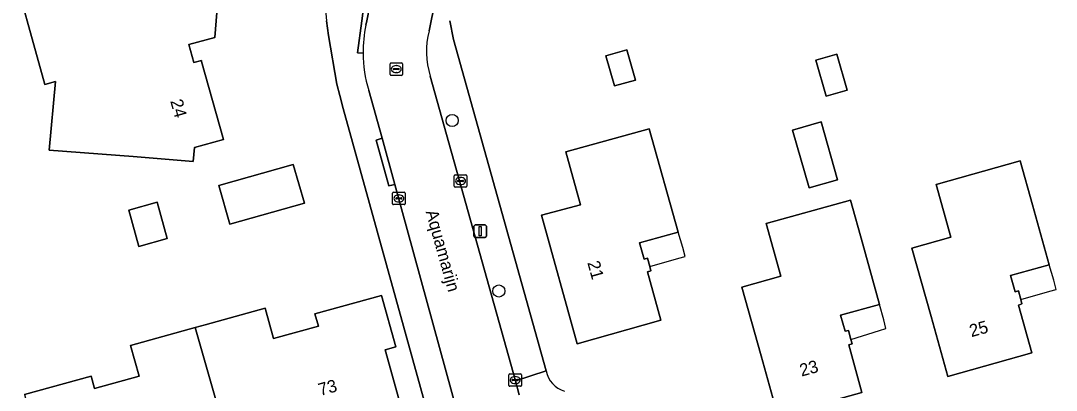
# Model space of a CAD drawing. Extents: x 159626 to 160723, y 388173 to 389416.
# Drawn here: x 159856.1 to 159939.1, y 388470.3 to 388500 of the extents above; entities that cross this region are included whole.
import ezdxf

# ---------------------------------------------------------------- set-up
doc = ezdxf.new("R2010")
doc.units = 0
for name, color, linetype in [('IMGEO_Boom', 7, 'Continuous'), ('IMGEO_Erf', 7, 'Continuous'), ('IMGEO_Kolk', 7, 'Continuous'), ('IMGEO_Lichtmast', 7, 'Continuous'), ('IMGEO_Openbare_ruimte_label', 7, 'Continuous'), ('IMGEO_Pand', 7, 'Continuous'), ('IMGEO_Pand_nummerreeks', 7, 'Continuous'), ('IMGEO_Pand_overbouw', 7, 'Continuous'), ('IMGEO_Rijbaan_lokaal_open', 7, 'Continuous'), ('IMGEO_Rioolput', 7, 'Continuous'), ('IMGEO_Voetpad_open', 7, 'Continuous')]:
    doc.layers.add(name, color=color, linetype=linetype)

msp = doc.modelspace()

# ---------------------------------------------------------------- linework, layer by layer
at = {"layer": 'IMGEO_Boom'}
for centre in [(159890.663, 388491.988), (159894.397, 388478.312)]:
    msp.add_circle(centre, 0.489, dxfattribs=at)
at = {"layer": 'IMGEO_Erf'}
for points in [[(159866.921, 388502.361), (159871.9, 388501.911), (159871.881, 388501.686), (159871.735, 388500), (159871.619, 388498.655), (159869.554, 388498.093), (159869.943, 388496.65), (159870.55, 388496.812), (159870.574, 388496.727), (159872.315, 388490.461), (159870.004, 388489.814), (159869.885, 388488.701), (159865.084, 388489.093), (159858.349, 388489.616), (159858.847, 388495.122), (159858.01, 388494.89), (159856.584, 388500), (159855.64, 388503.38)], [(159905.353, 388495.236), (159903.666, 388494.765), (159902.989, 388497.194), (159904.675, 388497.664)], [(159921.492, 388497.321), (159922.317, 388494.43), (159920.644, 388493.952), (159919.818, 388496.843)], [(159908.779, 388483.03), (159905.692, 388482.177), (159906.051, 388480.875), (159906.311, 388480.946), (159906.499, 388480.266), (159906.594, 388479.93), (159906.334, 388479.842), (159907.4, 388475.978), (159900.689, 388474.067), (159897.818, 388484.386), (159900.953, 388485.215), (159899.784, 388489.473), (159906.462, 388491.336)], [(159921.567, 388487.242), (159919.279, 388486.588), (159917.953, 388491.229), (159920.242, 388491.883)], [(159877.925, 388488.455), (159878.816, 388485.348), (159872.834, 388483.666), (159871.96, 388486.772)], [(159938.532, 388480.412), (159935.434, 388479.557), (159935.793, 388478.255), (159936.053, 388478.326), (159936.243, 388477.64), (159936.342, 388477.283), (159936.058, 388477.184), (159937.126, 388473.343), (159930.4, 388471.458), (159929.055, 388476.274), (159927.523, 388481.761), (159930.649, 388482.634), (159929.467, 388486.866), (159936.2, 388488.746), (159937.184, 388485.228)], [(159923.574, 388482.06), (159924.919, 388477.244), (159921.805, 388476.384), (159922.164, 388475.082), (159922.424, 388475.153), (159922.625, 388474.428), (159922.719, 388474.088), (159922.455, 388473.998), (159923.504, 388470.163), (159916.769, 388468.303), (159915.425, 388473.12), (159913.89, 388478.62), (159917.021, 388479.496), (159915.84, 388483.716), (159922.584, 388485.604)], [(159866.996, 388485.433), (159867.815, 388482.519), (159865.55, 388481.882), (159864.731, 388484.795)]]:
    msp.add_lwpolyline(points, close=True, dxfattribs=at)
for points in [[(159888.881, 388467.873), (159881.923, 388492.948), (159881.641, 388493.992), (159881.416, 388494.916), (159880.757, 388498.822), (159880.578, 388500)], [(159890.475, 388500), (159890.766, 388498.501), (159898.187, 388471.902)], [(159856.365, 388469.998), (159861.708, 388471.483), (159861.98, 388470.501), (159865.552, 388471.493), (159864.871, 388473.937), (159870.052, 388475.377), (159870.846, 388475.598), (159875.663, 388476.937), (159876.343, 388474.49), (159879.933, 388475.489), (159879.657, 388476.48), (159884.99, 388477.962), (159886.138, 388473.831), (159885.3, 388473.598), (159886.556, 388469.073)]]:
    msp.add_lwpolyline(points, dxfattribs=at)
for centre, radius, start, end in [((159893.604, 388501.361), 13.097, 165.53917, 185.96617), ((159900.306, 388472.34), 2.164, 191.67248, 253.04243)]:
    msp.add_arc(centre, radius, start, end, dxfattribs=at)
at = {"layer": 'IMGEO_Kolk'}
for p, q in [((159890.829, 388486.713), (159890.829, 388487.565)), ((159890.904, 388487.639), (159891.756, 388487.639)), ((159891.131, 388487.182), (159891.529, 388487.182)), ((159891.317, 388487.419), (159891.342, 388487.419)), ((159891.83, 388487.565), (159891.83, 388486.713)), ((159891.756, 388486.639), (159890.904, 388486.639)), ((159891.088, 388487.133), (159891.088, 388487.145)), ((159891.526, 388487.096), (159891.128, 388487.096)), ((159891.34, 388486.859), (159891.315, 388486.859)), ((159891.572, 388487.145), (159891.572, 388487.133)), ((159885.886, 388485.316), (159885.886, 388486.168)), ((159885.961, 388486.242), (159886.813, 388486.242)), ((159886.145, 388485.736), (159886.145, 388485.748)), ((159886.583, 388485.699), (159886.185, 388485.699)), ((159886.188, 388485.785), (159886.586, 388485.785)), ((159886.374, 388486.022), (159886.399, 388486.022)), ((159886.629, 388485.748), (159886.629, 388485.736)), ((159886.887, 388486.168), (159886.887, 388485.316)), ((159886.813, 388485.242), (159885.961, 388485.242)), ((159886.397, 388485.462), (159886.372, 388485.462)), ((159895.211, 388470.744), (159895.211, 388471.596)), ((159895.286, 388471.67), (159896.138, 388471.67)), ((159895.699, 388471.45), (159895.724, 388471.45)), ((159896.212, 388471.596), (159896.212, 388470.744)), ((159896.138, 388470.67), (159895.286, 388470.67)), ((159895.47, 388471.164), (159895.47, 388471.176)), ((159895.908, 388471.127), (159895.51, 388471.127)), ((159895.513, 388471.213), (159895.911, 388471.213)), ((159895.722, 388470.89), (159895.697, 388470.89)), ((159895.954, 388471.176), (159895.954, 388471.164))]:
    msp.add_line(p, q, dxfattribs=at)
for points in [[(159890.829, 388486.713), (159890.829, 388487.565)], [(159890.904, 388487.639), (159891.756, 388487.639)], [(159891.83, 388487.565), (159891.83, 388486.713)], [(159891.756, 388486.639), (159890.904, 388486.639)], [(159885.886, 388485.316), (159885.886, 388486.168)], [(159885.961, 388486.242), (159886.813, 388486.242)], [(159886.887, 388486.168), (159886.887, 388485.316)], [(159886.813, 388485.242), (159885.961, 388485.242)], [(159895.211, 388470.744), (159895.211, 388471.596)], [(159895.286, 388471.67), (159896.138, 388471.67)], [(159896.212, 388471.596), (159896.212, 388470.744)], [(159896.138, 388470.67), (159895.286, 388470.67)]]:
    msp.add_lwpolyline(points, dxfattribs=at)
for centre, radius, start, end in [((159890.906, 388487.563), 0.0765, 91.55205, 178.44795), ((159890.906, 388487.563), 0.0765, 91.55205, 178.44795), ((159891.128, 388487.142), 0.0403, 85.87752, 175.75265), ((159891.533, 388487.144), 0.0386, 1.73085, 96.63898), ((159891.754, 388487.563), 0.0765, 1.55205, 88.44795), ((159891.754, 388487.563), 0.0765, 1.55205, 88.44795), ((159890.906, 388486.715), 0.0765, 181.55205, 268.44795), ((159890.906, 388486.715), 0.0765, 181.55205, 268.44795), ((159891.125, 388487.132), 0.0366, 178.93798, 274.71019), ((159891.529, 388487.139), 0.043, 264.86636, 352.45326), ((159891.754, 388486.715), 0.0765, 271.55205, 358.44795), ((159891.754, 388486.715), 0.0765, 271.55205, 358.44795), ((159885.963, 388486.166), 0.0765, 91.55205, 178.44795), ((159885.963, 388486.166), 0.0765, 91.55205, 178.44795), ((159886.185, 388485.745), 0.0403, 85.87752, 175.75265), ((159886.182, 388485.735), 0.0366, 178.93798, 274.71019), ((159886.586, 388485.742), 0.043, 264.86636, 352.45326), ((159886.59, 388485.747), 0.0386, 1.73085, 96.63898), ((159886.811, 388486.166), 0.0765, 1.55205, 88.44795), ((159886.811, 388486.166), 0.0765, 1.55205, 88.44795), ((159885.963, 388485.318), 0.0765, 181.55205, 268.44795), ((159885.963, 388485.318), 0.0765, 181.55205, 268.44795), ((159886.811, 388485.318), 0.0765, 271.55205, 358.44795), ((159886.811, 388485.318), 0.0765, 271.55205, 358.44795), ((159895.288, 388471.594), 0.0765, 91.55205, 178.44795), ((159895.288, 388471.594), 0.0765, 91.55205, 178.44795), ((159896.136, 388471.594), 0.0765, 1.55205, 88.44795), ((159896.136, 388471.594), 0.0765, 1.55205, 88.44795), ((159895.288, 388470.746), 0.0765, 181.55205, 268.44795), ((159895.288, 388470.746), 0.0765, 181.55205, 268.44795), ((159895.51, 388471.173), 0.0403, 85.87752, 175.75265), ((159895.507, 388471.163), 0.0366, 178.93798, 274.71019), ((159895.911, 388471.17), 0.043, 264.86636, 352.45326), ((159895.915, 388471.175), 0.0386, 1.73085, 96.63898), ((159896.136, 388470.746), 0.0765, 271.55205, 358.44795), ((159896.136, 388470.746), 0.0765, 271.55205, 358.44795)]:
    msp.add_arc(centre, radius, start, end, dxfattribs=at)
for centre, major_axis, ratio, start_param, end_param in [((159891.316, 388487.139), (-0.387, 0.002), 0.722429, 4.712389, 7.853982), ((159891.341, 388487.139), (-0.39, 0.002), 0.717154, 1.570796, 4.712389), ((159886.373, 388485.742), (-0.387, 0.002), 0.722429, 4.712389, 7.853982), ((159886.398, 388485.742), (-0.39, 0.002), 0.717154, 1.570796, 4.712389), ((159895.698, 388471.17), (-0.387, 0.002), 0.722429, 4.712389, 7.853982), ((159895.723, 388471.17), (-0.39, 0.002), 0.717154, 1.570796, 4.712389)]:
    msp.add_ellipse(centre, major_axis=major_axis, ratio=ratio, start_param=start_param, end_param=end_param, dxfattribs=at)
at = {"layer": 'IMGEO_Lichtmast'}
for p, q in [((159892.41, 388482.71), (159892.41, 388483.51)), ((159892.41, 388483.51), (159892.41, 388482.71)), ((159892.51, 388483.61), (159893.3, 388483.61)), ((159893.3, 388483.61), (159892.51, 388483.61)), ((159893.4, 388483.51), (159893.4, 388482.71)), ((159893.4, 388482.71), (159893.4, 388483.51)), ((159893.3, 388482.61), (159892.51, 388482.61)), ((159892.51, 388482.61), (159893.3, 388482.61))]:
    msp.add_line(p, q, dxfattribs=at)
msp.add_lwpolyline([(159892.83, 388483.485), (159892.98, 388483.485), (159892.98, 388482.735), (159892.83, 388482.735), (159892.83, 388483.485)], dxfattribs=at)
for centre, start, end in [((159892.51, 388483.51), 90, 180), ((159892.51, 388483.51), 90, 180), ((159893.3, 388483.51), 0, 90), ((159893.3, 388483.51), 360, 90), ((159892.51, 388482.71), 180, 270), ((159892.51, 388482.71), 180, 270), ((159893.3, 388482.71), 270, 0), ((159893.3, 388482.71), 270, 0)]:
    msp.add_arc(centre, 0.1, start, end, dxfattribs=at)
at = {"layer": 'IMGEO_Pand'}
for points in [[(159869.554, 388498.093), (159871.619, 388498.655), (159871.735, 388500), (159871.881, 388501.686), (159871.9, 388501.911), (159866.921, 388502.361), (159855.64, 388503.38), (159856.584, 388500), (159858.01, 388494.89), (159858.847, 388495.122), (159858.349, 388489.616), (159865.084, 388489.093), (159869.885, 388488.701), (159870.004, 388489.814), (159872.315, 388490.461), (159870.574, 388496.727), (159870.55, 388496.812), (159869.943, 388496.65)], [(159905.353, 388495.236), (159904.675, 388497.664), (159902.989, 388497.194), (159903.666, 388494.765)], [(159919.818, 388496.843), (159920.644, 388493.952), (159922.317, 388494.43), (159921.492, 388497.321)], [(159906.499, 388480.266), (159906.311, 388480.946), (159906.051, 388480.875), (159905.692, 388482.177), (159908.779, 388483.03), (159906.462, 388491.336), (159899.784, 388489.473), (159900.953, 388485.215), (159897.818, 388484.386), (159900.689, 388474.067), (159907.4, 388475.978), (159906.334, 388479.842), (159906.594, 388479.93)], [(159921.567, 388487.242), (159920.242, 388491.883), (159917.953, 388491.229), (159919.279, 388486.588)], [(159872.834, 388483.666), (159878.816, 388485.348), (159877.925, 388488.455), (159871.96, 388486.772)], [(159938.532, 388480.412), (159937.184, 388485.228), (159936.2, 388488.746), (159929.467, 388486.866), (159930.649, 388482.634), (159927.523, 388481.761), (159929.055, 388476.274), (159930.4, 388471.458), (159937.126, 388473.343), (159936.058, 388477.184), (159936.342, 388477.283), (159936.243, 388477.64), (159936.053, 388478.326), (159935.793, 388478.255), (159935.434, 388479.557)], [(159915.425, 388473.12), (159916.769, 388468.303), (159923.504, 388470.163), (159922.455, 388473.998), (159922.719, 388474.088), (159922.625, 388474.428), (159922.424, 388475.153), (159922.164, 388475.082), (159921.805, 388476.384), (159924.919, 388477.244), (159923.574, 388482.06), (159922.584, 388485.604), (159915.84, 388483.716), (159917.021, 388479.496), (159913.89, 388478.62)], [(159864.731, 388484.795), (159865.55, 388481.882), (159867.815, 388482.519), (159866.996, 388485.433)], [(159870.052, 388475.377), (159873.439, 388463.52), (159877.039, 388464.539), (159876.552, 388466.292), (159886.556, 388469.073), (159885.3, 388473.598), (159886.138, 388473.831), (159884.99, 388477.962), (159879.657, 388476.48), (159879.933, 388475.489), (159876.343, 388474.49), (159875.663, 388476.937), (159870.846, 388475.598)], [(159870.052, 388475.377), (159864.871, 388473.937), (159865.552, 388471.493), (159861.98, 388470.501), (159861.708, 388471.483), (159856.365, 388469.998), (159857.517, 388465.859), (159858.355, 388466.092), (159859.613, 388461.567), (159869.615, 388464.359), (159870.121, 388462.581), (159873.439, 388463.52)]]:
    msp.add_lwpolyline(points, close=True, dxfattribs=at)
at = {"layer": 'IMGEO_Pand_overbouw'}
for points in [[(159906.499, 388480.266), (159908.823, 388480.939), (159909.346, 388481.09), (159909.15, 388481.791), (159908.779, 388483.03), (159905.692, 388482.177), (159906.051, 388480.875), (159906.311, 388480.946)], [(159936.243, 388477.64), (159938.587, 388478.298), (159939.096, 388478.44), (159938.892, 388479.171), (159938.532, 388480.412), (159935.434, 388479.557), (159935.793, 388478.255), (159936.053, 388478.326)], [(159922.625, 388474.428), (159924.925, 388475.148), (159925.435, 388475.298), (159925.263, 388475.998), (159924.919, 388477.244), (159921.805, 388476.384), (159922.164, 388475.082), (159922.424, 388475.153)]]:
    msp.add_lwpolyline(points, close=True, dxfattribs=at)
at = {"layer": 'IMGEO_Rijbaan_lokaal_open'}
for points in [[(159891.183, 388510.696), (159891.947, 388514.397), (159892.354, 388516.331), (159887.444, 388517.371), (159887.266, 388516.517), (159886.024, 388510.573), (159884.068, 388501.214), (159883.818, 388500), (159883.746, 388499.648)], [(159888.805, 388499.176), (159888.975, 388500), (159891.183, 388510.696)], [(159896.031, 388469.976), (159895.725, 388471.119), (159888.9, 388495.554)], [(159883.978, 388494.409), (159885.035, 388490.563), (159886.052, 388486.862), (159891.179, 388468.207), (159891.191, 388468.159), (159891.502, 388466.929)]]:
    msp.add_lwpolyline(points, dxfattribs=at)
for centre, radius, start, end in [((159893.304, 388497.573), 9.781, 167.75187, 181.04847), ((159895.22, 388497.532), 6.623, 165.62715, 197.37773), ((159893.024, 388497.309), 9.499, 179.48542, 197.77317)]:
    msp.add_arc(centre, radius, start, end, dxfattribs=at)
at = {"layer": 'IMGEO_Rioolput'}
for p, q in [((159885.681, 388495.69), (159885.681, 388496.542)), ((159885.756, 388496.616), (159886.608, 388496.616)), ((159886.169, 388496.396), (159886.194, 388496.396)), ((159886.682, 388496.542), (159886.682, 388495.69)), ((159886.608, 388495.616), (159885.756, 388495.616)), ((159885.94, 388496.11), (159885.94, 388496.122)), ((159886.378, 388496.073), (159885.98, 388496.073)), ((159885.983, 388496.159), (159886.381, 388496.159)), ((159886.192, 388495.836), (159886.167, 388495.836)), ((159886.424, 388496.122), (159886.424, 388496.11))]:
    msp.add_line(p, q, dxfattribs=at)
for points in [[(159885.681, 388495.69), (159885.681, 388496.542)], [(159885.756, 388496.616), (159886.608, 388496.616)], [(159886.682, 388496.542), (159886.682, 388495.69)], [(159886.608, 388495.616), (159885.756, 388495.616)]]:
    msp.add_lwpolyline(points, dxfattribs=at)
for centre, radius, start, end in [((159885.758, 388496.54), 0.0765, 91.55205, 178.44795), ((159885.758, 388496.54), 0.0765, 91.55205, 178.44795), ((159886.606, 388496.54), 0.0765, 1.55205, 88.44795), ((159886.606, 388496.54), 0.0765, 1.55205, 88.44795), ((159885.758, 388495.692), 0.0765, 181.55205, 268.44795), ((159885.758, 388495.692), 0.0765, 181.55205, 268.44795), ((159885.98, 388496.119), 0.0403, 85.87752, 175.75265), ((159885.977, 388496.109), 0.0366, 178.93798, 274.71019), ((159886.381, 388496.116), 0.043, 264.86636, 352.45326), ((159886.385, 388496.121), 0.0386, 1.73085, 96.63898), ((159886.606, 388495.692), 0.0765, 271.55205, 358.44795), ((159886.606, 388495.692), 0.0765, 271.55205, 358.44795)]:
    msp.add_arc(centre, radius, start, end, dxfattribs=at)
for centre, major_axis, ratio, start_param, end_param in [((159886.168, 388496.116), (-0.387, 0.002), 0.722429, 4.712389, 7.853982), ((159886.193, 388496.116), (-0.39, 0.002), 0.717154, 1.570796, 4.712389)]:
    msp.add_ellipse(centre, major_axis=major_axis, ratio=ratio, start_param=start_param, end_param=end_param, dxfattribs=at)
at = {"layer": 'IMGEO_Voetpad_open'}
for points in [[(159902.255, 388561.334), (159901.147, 388556.088), (159900.706, 388556.171), (159898.454, 388545.528), (159898.89, 388545.443), (159897.836, 388540.231), (159897.401, 388540.306), (159895.037, 388529.114), (159895.483, 388529.036), (159894.551, 388524.568), (159894.104, 388524.658), (159892.92, 388519.028), (159892.354, 388516.331), (159891.947, 388514.397), (159892.396, 388514.299), (159891.629, 388510.607), (159891.183, 388510.696), (159888.975, 388500), (159888.805, 388499.176)], [(159883.746, 388499.648), (159883.818, 388500), (159884.068, 388501.214), (159883.581, 388501.229), (159883.419, 388500), (159883.079, 388497.41), (159883.525, 388497.394)], [(159883.525, 388497.394), (159883.079, 388497.41), (159883.419, 388500), (159883.581, 388501.229), (159884.068, 388501.214)], [(159880.578, 388500), (159880.757, 388498.822), (159881.416, 388494.916), (159881.641, 388493.992), (159881.923, 388492.948), (159888.881, 388467.873), (159891.179, 388468.207), (159886.052, 388486.862), (159885.577, 388486.741), (159884.562, 388490.425), (159885.035, 388490.563), (159883.978, 388494.409)], [(159890.766, 388498.501), (159890.475, 388500)], [(159888.9, 388495.554), (159895.725, 388471.119), (159898.187, 388471.902), (159890.766, 388498.501)], [(159898.187, 388471.902), (159895.725, 388471.119), (159896.031, 388469.976)]]:
    msp.add_lwpolyline(points, dxfattribs=at)
msp.add_lwpolyline([(159885.035, 388490.563), (159884.562, 388490.425), (159885.577, 388486.741), (159886.052, 388486.862)], close=True, dxfattribs=at)
for centre, radius, start, end in [((159893.604, 388501.361), 13.097, 165.53917, 185.96617), ((159893.304, 388497.573), 9.781, 167.75187, 181.04847), ((159895.22, 388497.532), 6.623, 165.62715, 197.37773), ((159893.024, 388497.309), 9.499, 179.48542, 197.77317), ((159900.306, 388472.34), 2.164, 191.67248, 253.04243)]:
    msp.add_arc(centre, radius, start, end, dxfattribs=at)

# ---------------------------------------------------------------- texts
at = {"layer": 'IMGEO_Openbare_ruimte_label'}
msp.add_text('Aquamarijn', height=1, rotation=285.66211, dxfattribs=at).set_placement((159888.529, 388484.674))
at = {"layer": 'IMGEO_Pand_nummerreeks'}
for s, rotation, p in [('24', 285.53268, (159868.05, 388493.554)), ('21', 285.54788, (159901.489, 388480.589)), ('25', 15.65583, (159932.287, 388474.604)), ('23', 15.43852, (159918.67, 388471.442)), ('73', 15.53534, (159880.083, 388469.889))]:
    msp.add_text(s, height=1, rotation=rotation, dxfattribs=at).set_placement(p)

doc.saveas('drawing.dxf')
